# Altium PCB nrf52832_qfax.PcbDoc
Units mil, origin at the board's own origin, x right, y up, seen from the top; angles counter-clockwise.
Board outline 700 x 538.01 mil, 2 copper layers (Top Layer, Bottom Layer), stack 65.8 mil thick; 18 components, 44 nets, 86 pads, 53 vias.
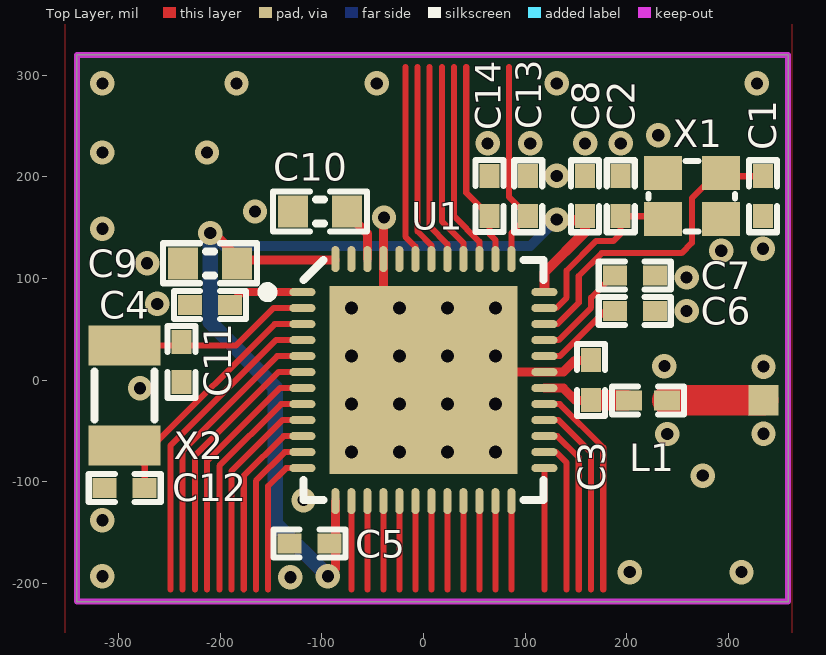
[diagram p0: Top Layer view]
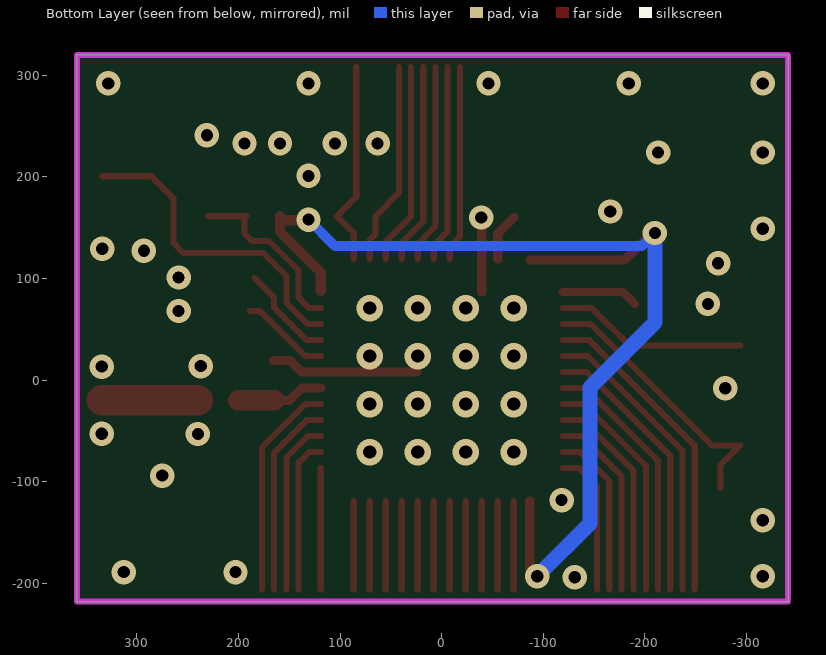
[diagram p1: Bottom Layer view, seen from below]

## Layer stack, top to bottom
Top Solder: solder mask 0.4, Solder Resist, Dk 3.5
Top Layer: signal copper 1.4
Dielectric1: core 63, FR-4, Dk 4.8
Bottom Layer: signal copper 1.4
Bottom Solder: solder mask 0.4, Solder Resist, Dk 3.5

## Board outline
-341,-218 359,-218 359,320.01 -341,320.01

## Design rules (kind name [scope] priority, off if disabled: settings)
AssemblyTestPointUsage [All] p0: scope1count=1 scope1_0_kind=Board scope1_0_value=Board scope2count=1 scope2_0_kind=Board scope2_0_value=Board commentlength=0
AssemblyTestpoint [All] p0: scope1count=1 scope1_0_kind=Board scope1_0_value=Board scope2count=1 scope2_0_kind=Board scope2_0_value=Board commentlength=0
Clearance Polygon [All] p0 off: scope1count=1 scope1_0_kind=Board scope1_0_value=Board scope2count=1 scope2_0_kind=Board scope2_0_value=Board commentlength=112 gap=10 // Protel DXP Scope 1 Expression Was: (InNamedPolygon('Top_Layer-GND')) or (InNamedPolygon('Bottom_Layer-GND'))
Clearance Polygon_ANT [All] p0 off: scope1count=1 scope1_0_kind=Board scope1_0_value=Board scope2count=1 scope2_0_kind=Net scope2_0_value=RF commentlength=112 gap=5 // Protel DXP Scope 1 Expression Was: (InNamedPolygon('Top_Layer-GND')) or (InNamedPolygon('Bottom_Layer-GND'))
Clearance [All] p0: scope1count=1 scope1_0_kind=Board scope1_0_value=Board scope2count=1 scope2_0_kind=Board scope2_0_value=Board commentlength=0 gap=6
Clearance Polygon_ANT [(InNamedPolygon('Top_Layer-GND')) or (InNamedPolygon('Bottom_Layer-GND')) vs InNet('RF')] p1: gap=5 ignorepadtopadclearanceinfootprint=FALSE except(0: Arc-Hole Track-Hole SMDPad-Hole THPad-Hole Via-Hole Fill-Hole Poly-Hole Region-Hole Text-Hole)
Clearance Polygon [(InNamedPolygon('Top_Layer-GND')) or (InNamedPolygon('Bottom_Layer-GND'))] p2: gap=10 ignorepadtopadclearanceinfootprint=FALSE except(0: Arc-Hole Track-Hole SMDPad-Hole THPad-Hole Via-Hole Fill-Hole Poly-Hole Region-Hole Text-Hole)
Clearance [All] p3: gap=6 ignorepadtopadclearanceinfootprint=FALSE except(0: Arc-Hole Track-Hole SMDPad-Hole THPad-Hole Via-Hole Fill-Hole Poly-Hole Region-Hole Text-Hole)
ComponentClearance [All] p0 off: scope1count=1 scope1_0_kind=Board scope1_0_value=Board scope2count=1 scope2_0_kind=Board scope2_0_value=Board commentlength=0 gap=10 collisioncheckmode=3
ComponentClearance [All] p1 off: gap=10 collisioncheckmode=3 verticalgap=10 showdistances=FALSE
DiffPairsRouting [All] p0: scope1count=1 scope1_0_kind=Board scope1_0_value=Board scope2count=1 scope2_0_kind=Board scope2_0_value=Board commentlength=0
FabricationTestPointUsage TestPointUsage [All] p0: scope1count=1 scope1_0_kind=Board scope1_0_value=Board scope2count=1 scope2_0_kind=Board scope2_0_value=Board commentlength=0 valid=0 allowmultiple=FALSE
FabricationTestPointUsage TestPointUsage [All] p1: valid=0 allowmultiple=FALSE
FabricationTestpoint Testpoint [All] p0: scope1count=1 scope1_0_kind=Board scope1_0_value=Board scope2count=1 scope2_0_kind=Board scope2_0_value=Board commentlength=0 side=3 testpointundercomponent=TRUE minsize=40 maxsize=100 preferedsize=60 minholesize=0 maxholesize=40 preferedholesize=32 testpointgrid=1
FabricationTestpoint Testpoint [All] p1: side=3 testpointundercomponent=TRUE minsize=40 maxsize=100 preferedsize=60 minholesize=0 maxholesize=40 preferedholesize=32 testpointgrid=1 allowsidetop=TRUE allowsidebottom=TRUE usegrid=TRUE gridtolerance=0.01
FanoutControl Fanout_Default [All] p0: scope1count=1 scope1_0_kind=Board scope1_0_value=Board scope2count=1 scope2_0_kind=Board scope2_0_value=Board commentlength=30 // Fanout_Default (Default Rule)
FanoutControl Fanout_Small [All] p0 off: scope1count=1 scope1_0_kind=Board scope1_0_value=Board scope2count=1 scope2_0_kind=Board scope2_0_value=Board commentlength=84 // Protel DXP Scope 1 Expression Was: (CompPinCount < 5)   Fanout_Small (Default Rule)
FanoutControl Fanout_SOIC [All] p0 off: scope1count=1 scope1_0_kind=Board scope1_0_value=Board scope2count=1 scope2_0_kind=Board scope2_0_value=Board commentlength=71 // Protel DXP Scope 1 Expression Was: IsSOIC   Fanout_SOIC (Default Rule)
FanoutControl Fanout_LCC [All] p0 off: scope1count=1 scope1_0_kind=Board scope1_0_value=Board scope2count=1 scope2_0_kind=Board scope2_0_value=Board commentlength=69 // Protel DXP Scope 1 Expression Was: IsLCC   Fanout_LCC (Default Rule)
FanoutControl Fanout_BGA [All] p0 off: scope1count=1 scope1_0_kind=Board scope1_0_value=Board scope2count=1 scope2_0_kind=Board scope2_0_value=Board commentlength=69 // Protel DXP Scope 1 Expression Was: IsBGA   Fanout_BGA (Default Rule)
Height [All] p0 off: scope1count=1 scope1_0_kind=Board scope1_0_value=Board scope2count=1 scope2_0_kind=Board scope2_0_value=Board commentlength=0
Height [All] p1 off: minheight=0 maxheight=1000 prefheight=500
HoleSize [All] p0: scope1count=1 scope1_0_kind=Board scope1_0_value=Board scope2count=1 scope2_0_kind=Board scope2_0_value=Board commentlength=0 absolutevalues=TRUE maxlimit=160 minlimit=12 maxpercent=80.000 minpercent=20.000
HoleSize [All] p1: absolutevalues=TRUE maxlimit=160 minlimit=12 maxpercent=80.000 minpercent=20.000
HoleToHoleClearance [All] p0: scope1count=1 scope1_0_kind=Board scope1_0_value=Board scope2count=1 scope2_0_kind=Board scope2_0_value=Board commentlength=0
LayerPairs [All] p0: scope1count=1 scope1_0_kind=Board scope1_0_value=Board scope2count=1 scope2_0_kind=Board scope2_0_value=Board commentlength=0 enforce=TRUE
MinimumAnnularRing [All] p0 off: scope1count=1 scope1_0_kind=Board scope1_0_value=Board scope2count=1 scope2_0_kind=Board scope2_0_value=Board commentlength=0 minimumring=6
MinimumAnnularRing [All] p1 off: minimumring=6
MinimumSolderMaskSliver [All] p0: scope1count=1 scope1_0_kind=Board scope1_0_value=Board scope2count=1 scope2_0_kind=Board scope2_0_value=Board commentlength=0
NetAntennae [All] p0: scope1count=1 scope1_0_kind=Board scope1_0_value=Board scope2count=1 scope2_0_kind=Board scope2_0_value=Board commentlength=0
PasteMaskExpansion [All] p0: scope1count=1 scope1_0_kind=Board scope1_0_value=Board scope2count=1 scope2_0_kind=Board scope2_0_value=Board commentlength=0 expansion=0
PlaneClearance [All] p0: scope1count=1 scope1_0_kind=Board scope1_0_value=Board scope2count=1 scope2_0_kind=Board scope2_0_value=Board commentlength=0 clearance=20
PlaneConnect [All] p0: scope1count=1 scope1_0_kind=Board scope1_0_value=Board scope2count=1 scope2_0_kind=Board scope2_0_value=Board commentlength=0 planeconnectstyle=Relief reliefexpansion=20 reliefentries=4 reliefconductorwidth=10 reliefairgap=10
PolygonConnect [All] p0: scope1count=1 scope1_0_kind=Board scope1_0_value=Board scope2count=1 scope2_0_kind=Board scope2_0_value=Board commentlength=0 connectstyle=Relief reliefconductorwidth=10 reliefentries=4 polygonreliefangle="90 Angle"
PolygonConnect PolygonConnect_1 [All] p0 off: scope1count=1 scope1_0_kind=Board scope1_0_value=Board scope2count=1 scope2_0_kind=Board scope2_0_value=Board commentlength=59 connectstyle=Direct reliefconductorwidth=10 reliefentries=4 polygonreliefangle="90 Angle" // Protel DXP Scope 1 Expression Was: isVia and innet(gnd)
PolygonConnect PolygonConnect_1 [isVia and innet(gnd)] p1: connectstyle=Direct reliefconductorwidth=10 reliefentries=4 polygonreliefangle="90 Angle" airgapwidth=10
PolygonConnect [All] p2: connectstyle=Relief reliefconductorwidth=10 reliefentries=4 polygonreliefangle="90 Angle" airgapwidth=10
RoutingCorners [All] p0: scope1count=1 scope1_0_kind=Board scope1_0_value=Board scope2count=1 scope2_0_kind=Board scope2_0_value=Board commentlength=0 cornerstyle=45-Degree minsetback=100 maxsetback=100
RoutingLayers [All] p0: scope1count=1 scope1_0_kind=Board scope1_0_value=Board scope2count=1 scope2_0_kind=Board scope2_0_value=Board commentlength=0 top layer=Automatic bottom layer=Automatic
RoutingPriority [All] p0: scope1count=1 scope1_0_kind=Board scope1_0_value=Board scope2count=1 scope2_0_kind=Board scope2_0_value=Board commentlength=0
RoutingTopology [All] p0: scope1count=1 scope1_0_kind=Board scope1_0_value=Board scope2count=1 scope2_0_kind=Board scope2_0_value=Board commentlength=0 topology=Shortest
RoutingVias [All] p0: scope1count=1 scope1_0_kind=Board scope1_0_value=Board scope2count=1 scope2_0_kind=Board scope2_0_value=Board commentlength=0 holewidth=16 width=32 viastyle="Through Hole" minholewidth=10 minwidth=10 maxholewidth=28 maxwidth=50
RoutingVias [All] p1: holewidth=16 width=32 viastyle="Through Hole" minholewidth=10 minwidth=10 maxholewidth=28 maxwidth=50
ShortCircuit [All] p0: scope1count=1 scope1_0_kind=Board scope1_0_value=Board scope2count=1 scope2_0_kind=Board scope2_0_value=Board commentlength=0 allowed=FALSE
SilkToBoardRegionClearance [All] p0: scope1count=1 scope1_0_kind=Board scope1_0_value=Board scope2count=1 scope2_0_kind=Board scope2_0_value=Board commentlength=0
SilkToSilkClearance [All] p0: scope1count=1 scope1_0_kind=Board scope1_0_value=Board scope2count=1 scope2_0_kind=Board scope2_0_value=Board commentlength=0
SilkToSolderMaskClearance SilkscreenOverComponentPads [All] p0 off: scope1count=1 scope1_0_kind=Board scope1_0_value=Board scope2count=1 scope2_0_kind=Board scope2_0_value=Board commentlength=44 // Protel DXP Scope 1 Expression Was: IsPad
SilkToSolderMaskClearance SilkscreenOverComponentPads [IsPad] p1: minsilkscreentomaskgap=10 clearancetoexposedcopper=TRUE
SolderMaskExpansion [All] p0: scope1count=1 scope1_0_kind=Board scope1_0_value=Board scope2count=1 scope2_0_kind=Board scope2_0_value=Board commentlength=0 expansion=3
SolderMaskExpansion [All] p1: expansion=3
UnRoutedNet [All] p0: scope1count=1 scope1_0_kind=Board scope1_0_value=Board scope2count=1 scope2_0_kind=Board scope2_0_value=Board commentlength=0
UnpouredPolygon [All] p0: scope1count=1 scope1_0_kind=Board scope1_0_value=Board scope2count=1 scope2_0_kind=Board scope2_0_value=Board commentlength=0
Width [All] p0: scope1count=1 scope1_0_kind=Board scope1_0_value=Board scope2count=1 scope2_0_kind=Board scope2_0_value=Board commentlength=0 maxlimit=100 minlimit=6 preferedwidth=6
Width [All] p1: maxlimit=100 minlimit=6 preferedwidth=6
24 further rules are at their usual default settings.

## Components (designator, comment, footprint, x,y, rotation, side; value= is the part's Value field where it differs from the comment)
C1 "12pF" CAPC1005X04L 334.15,181.01 r270 top
C2 "12pF" CAPC1005X04L 194.15,181.01 r90 top
C3 "0.8pF" CAPC1005X04L 165,0 r270 top
C4 "100nF" CAPC1005X04L -210,74 r180 top
C5 "100nF" CAPC1005X04L -112,-161 r180 top
C6 "N.C." CAPC1005X04L 208,68 r180 top
C7 "100pF" CAPC1005X04L 208,103 r0 top
C8 "100nF" CAPC1005X04L 159.15,181.01 r90 top
C9 "4.7µF" CAPC1608X06L -210,115 r180 top
C10 "1.0µF" CAPC1608X06L -101.85,166.01 r0 top
C11 "12pF" CAPC1005X04L -238,18 r270 top
C12 "12pF" CAPC1005X04L -294,-106 r180 top
C13 "" CAPC1005X04L 103.15,181.01 r90 top
C14 "12pF" CAPC1005X04L 65.15,181.09 r90 top
L1 "3.9nH" INDC1005X04L 221,-20 r0 top
U1 "nRF52832-QFAA" QFN40P600X600X90-48N 0,0 r0 top locked
X1 "32MHz" BT-XTAL_2016 264.15,181.01 r180 top
X2 "32.768kHz" XTAL_3215 -294,-15 r270 top

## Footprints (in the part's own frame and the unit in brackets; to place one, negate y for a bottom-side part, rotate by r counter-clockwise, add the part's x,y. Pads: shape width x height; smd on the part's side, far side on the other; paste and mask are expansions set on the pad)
BT-XTAL_2016 [mm] "Crystal 2.0 x 1.6 mm"
  rect 0.95x0.85 smd: 1(-0.725,-0.575) 2(0.725,-0.575) 3(0.725,0.575) 4(-0.725,0.575)
  silkscreen extent -1.08,-0.88 1.08,0.88
CAPC1005X04L [mm] "Chip Capacitor, 2-Leads, Body 1.0x0.5mm, IPC High Density"
  rect 0.6x0.5 smd: 1(-0.5,0) 2(0.5,0)
  silkscreen extent -0.9,-0.35 0.9,0.35
CAPC1608X06L [mm] "Chip Capacitor, 2-Leads, Body 1.6x0.8mm, IPC High Density"
  rect 0.75x0.8 smd: 1(-0.675,0) 2(0.675,0)
  silkscreen extent -1.17,-0.5 1.17,0.5
INDC1005X04L [mm] "Chip Inductor, 2-Leads, Body 1.0x0.5mm, IPC High Density"
  rect 0.65x0.5 smd: 1(-0.475,0) 2(0.475,0)
  silkscreen extent -0.9,-0.35 0.9,0.35
QFN40P600X600X90-48N [mm] "QFN, 48-Leads, Body 6,0x6,0mm (max), Pitch 0,40mm, IPC Medium Density"
  oval 0.65x0.2 smd: 1(-3.025,2.2) 2(-3.025,1.8) 3(-3.025,1.4) 4(-3.025,1) 5(-3.025,0.6) 6(-3.025,0.2) 7(-3.025,-0.2) 8(-3.025,-0.6) 9(-3.025,-1) 10(-3.025,-1.4) 11(-3.025,-1.8) 12(-3.025,-2.2) 25(3.025,-2.2) 26(3.025,-1.8) 27(3.025,-1.4) 28(3.025,-1) 29(3.025,-0.6) 30(3.025,-0.2) 31(3.025,0.2) 32(3.025,0.6) 33(3.025,1) 34(3.025,1.4) 35(3.025,1.8) 36(3.025,2.2)
  oval 0.2x0.65 smd: 13(-2.2,-3.025) 14(-1.8,-3.025) 15(-1.4,-3.025) 16(-1,-3.025) 17(-0.6,-3.025) 18(-0.2,-3.025) 19(0.2,-3.025) 20(0.6,-3.025) 21(1,-3.025) 22(1.4,-3.025) 23(1.8,-3.025) 24(2.2,-3.025) 37(2.2,3.025) 38(1.8,3.025) 39(1.4,3.025) 40(1,3.025) 41(0.6,3.025) 42(0.2,3.025) 43(-0.2,3.025) 44(-0.6,3.025) 45(-1,3.025) 46(-1.4,3.025) 47(-1.8,3.025) 48(-2.2,3.025)
  rect 4.7x4.7 smd: 49(0,0)
  silkscreen extent -4.02,-3 3,3
XTAL_3215 [mm] "XTAL SMD 3.2 x 1.5 mm"
  rect 1x1.8 smd: 1(-1.25,0) 2(1.25,0)
  silkscreen extent -0.6,-0.75 0.6,0.75

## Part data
C1 C2 C11 C12 C13 C14: library part C0402-12p, "Capacitor, NP0, ±2%"
C3: library part C0402-0.8p, "Capacitor, NP0, ±5%"
C4 C5 C8: library part C0402-100n, "Capacitor, X7R, ±10%"
C6: library part C0402-N.C., "Not mounted"
C7: library part C0402-100p, "Capacitor, NP0, ±5%"
C9: library part C0603-4µ7, "Capacitor, X5R, ±10%"
C10: library part C0603-1µ0, "Capacitor, X7R, ±10%"
L1: library part L0402-3n9, "High frequency chip inductor ±5%"
U1: "Multi-protocol Bluetooth Low Energy, ANT and 2.4GHz proprietary system-on-chip"
X1: library part XTAL_SMD2016_32MHz_8pF_General, "XTAL SMD 2016, 32MHz, Cl=8pF, Total Tol: ±40ppm"
X2: library part XTAL_SMD3215_32.768kHz_9pF_General, "XTAL SMD 3215, 32.768kHz, Cl=9pF, Total Tol: ±50ppm"

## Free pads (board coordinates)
  rect 30x30 smd: 0(334.7,-19.75)

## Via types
v1: diameter 24, hole 12, Top Layer to Bottom Layer, tented both sides, 37 vias
v2: diameter 25.98, hole 12.99, Top Layer to Bottom Layer, tented both sides, 16 vias

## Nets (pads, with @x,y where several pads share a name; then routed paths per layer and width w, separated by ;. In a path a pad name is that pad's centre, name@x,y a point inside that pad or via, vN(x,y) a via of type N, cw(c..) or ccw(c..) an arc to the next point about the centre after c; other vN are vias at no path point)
DEC1: C4.1 U1.1 | length 76
  Top Layer w8: C4.1@-190.16,74.76 -178.31,86.61 U1.1
DEC2: C6.2 U1.32 | length 88.3
  Top Layer w6: U1.32 134.3,23.62 178.67,68 C6.2@189,68
DEC3: C7.1 U1.33 | length 96
  Top Layer w6: U1.33 133.07,39.37 165,71.3 165,81.19 C7.1@184.06,100.25
DEC4: C10.2 U1.46 | length 47.8
  Top Layer w9: C10.2@-71.26,160.19 -55.12,144.05 U1.46
GND: C1.2 C2.2 C3.1 C4.2 C5.2 C6.1 C7.2 C8.2 C9.2 C10.1 C11.2 C12.2 C13.2 C14.2 U1.31 U1.45 U1.49 X1.2 X1.4 | length 219.1
  Top Layer w9: U1.49@-39.37,86.61 U1.45 v1@-39.37,160.01 ; U1.49@24.31,8 137.77,8 149.06,19.3 C3.1@165.31,19.3
  other v1: -131,-194 -316,-193 203,-189 313,-189 -316,-138 -118,-118.11 275,-94 240,-53 334.7,-52.75 -279,-8 334.7,13.25 237.16,13.76 259,68 -262,75 259,101 -272,115 293.15,127.32 334.15,129.32 -316,149 -38.85,160.01 -165.85,166.01 131.15,201.01 -316,224 -213,224 63.15,233.01 105.15,233.01 159.15,233.01 194.15,233.01 231.15,241.01 -316,292 -184,292 -46,292 131.15,292.01 328.16,292
  other v2: -70.87,-70.87 -23.62,-70.87 23.62,-70.87 70.87,-70.87 -70.87,-23.62 -23.62,-23.62 23.62,-23.62 70.87,-23.62 -70.87,23.62 -23.62,23.62 23.62,23.62 70.87,23.62 -70.87,70.87 -23.62,70.87 23.62,70.87 70.87,70.87
NetC3_2: C3.2 L1.1 U1.30 | length 86.6
  Top Layer w9: U1.30 137.79,-7.87 149.99,-20.07 C3.2@165.32,-20.07
  Top Layer w20: C3.2@165,-19.87 L1.1@200.31,-19.87
P0.00/XL1: C11.1 U1.2 X2.1 | length 190.1
  Top Layer w6: X2.1 -184.36,34.21 -147.71,70.87 U1.2
P0.01/XL2: C12.1 U1.3 X2.2 | length 274.3
  Top Layer w6: C12.1 -274.32,-83.9 X2.2 -265.82,-64.21 -146.49,55.12 U1.3
P0.02/AIN0: U1.4 | length 314.3
  Top Layer w6: -249,-205.81 -249,-64.39 -145.24,39.37 U1.4
P0.03/AIN1: U1.5 | length 292.8
  Top Layer w6: -236.98,-205.81 -236.98,-69.37 -143.98,23.62 U1.5
P0.04/AIN2: U1.6 | length 271.4
  Top Layer w6: -224.96,-205.81 -224.96,-74.35 -142.73,7.87 U1.6
P0.05/AIN3: U1.7 | length 249.8
  Top Layer w6: -212.85,-205.81 -212.85,-79.37 -141.36,-7.87 U1.7
P0.06: U1.8 | length 228.4
  Top Layer w6: -200.85,-205.81 -200.85,-84.34 -140.14,-23.62 U1.8
P0.07: U1.9 | length 206.9
  Top Layer w6: -188.85,-205.81 -188.85,-89.31 -138.92,-39.37 U1.9
P0.08: U1.10 | length 185.5
  Top Layer w6: -176.85,-205.81 -176.85,-94.28 -137.7,-55.12 U1.10
P0.09: U1.11 | length 164.1
  Top Layer w6: -164.85,-205.81 -164.85,-99.25 -136.47,-70.87 U1.11
P0.10: U1.12 | length 142.6
  Top Layer w6: -152.85,-205.81 -152.85,-104.22 -135.25,-86.61 U1.12
P0.11: U1.14 | length 86.9
  Top Layer w6: -70.87,-206 U1.14
P0.12: U1.15 | length 86.9
  Top Layer w6: -55.12,-206 U1.15
P0.13: U1.16 | length 86.9
  Top Layer w6: -39.37,-206 U1.16
P0.14: U1.17 | length 86.9
  Top Layer w6: -23.62,-206 U1.17
P0.15: U1.18 | length 86.9
  Top Layer w6: -7.87,-206 U1.18
P0.16: U1.19 | length 86.9
  Top Layer w6: 7.87,-206 U1.19
P0.17: U1.20 | length 86.9
  Top Layer w6: 23.62,-206 U1.20
P0.18: U1.21 | length 86.9
  Top Layer w6: 39.37,-206 U1.21
P0.19: U1.22 | length 86.9
  Top Layer w6: 55.12,-206 U1.22
P0.20: U1.23 | length 86.9
  Top Layer w6: 70.87,-206 U1.23
P0.21: U1.24 | length 86.9
  Top Layer w6: 86.61,-206 U1.24
P0.22: U1.27 | length 172.4
  Top Layer w6: U1.27 131.85,-55.12 152.89,-76.16 152.89,-206
P0.23: U1.28 | length 193.8
  Top Layer w6: U1.28 133.07,-39.37 165,-71.3 165,-206
P0.24: U1.29 | length 215.3
  Top Layer w6: U1.29 134.3,-23.62 177,-66.33 177,-206
P0.25: C13.1 U1.37 | length 203.6
  Top Layer w6: 84.15,308.01 84.15,180.32 C13.1 86.61,144.78 U1.37
P0.26: C14.1 U1.38 | length 201.9
  Top Layer w6: 42.15,308.01 42.15,184.41 C14.1@64.15,162.41 ; C14.1@64.15,161.32 C14.1@64.15,162.41 ; U1.38 70.87,138.02 65.15,143.73 C14.1 C14.1@64.15,162.41
P0.27: U1.39 | length 199.3
  Top Layer w6: 30.15,308.01 30.15,161.32 55.12,136.35 U1.39
P0.28/AIN4: U1.40 | length 197.7
  Top Layer w6: 18.15,308.01 18.15,156.29 39.37,135.07 U1.40
P0.29/AIN5: U1.41 | length 196.1
  Top Layer w6: 6.15,308.01 6.15,151.32 23.62,133.85 U1.41
P0.30/AIN6: U1.42 | length 194.6
  Top Layer w6: -5.85,308.01 -5.85,146.32 7.87,132.6 U1.42
P0.31/AIN7: U1.43 | length 193
  Top Layer w6: -17.85,308.01 -17.85,141.32 -7.87,131.35 U1.43
RF: L1.2 pad.0 | length 94.7
  Top Layer w30: L1.2@240.02,-19.75 pad.0
SWDCLK: U1.25 | length 119.4
  Top Layer w6: 119.09,-206 U1.25
SWDIO: U1.26 | length 150.8
  Top Layer w6: U1.26 130.5,-70.87 140.89,-81.26 140.89,-206
VDD_NRF: C5.1 C8.1 C9.1 U1.13 U1.36 U1.48 | length 1075.8
  Top Layer w9: v1(-209.84,144.76) -206.58,144.76 -179.92,118.11 U1.48@-87,118.11 ; v1(-94,-193) -86.61,-185.61 U1.13
  Top Layer w10: U1.36@119.09,88.01 119.09,105.95 159.15,146 C8.1 159.15,157.32 131.84,157.32 v1(131.15,158.01)
  Bottom Layer w10: v1(-209.84,144.76) -197.08,132 105.14,132 v1(131.15,158.01)
  Bottom Layer w15: v1(-209.84,144.76) -209.84,56.66 -145.95,-7.24 -145.95,-141.05 v1(-94,-193)
XC1: C1.1 U1.34 X1.1 | length 316.5
  Top Layer w6: U1.34 131.85,55.12 152.89,76.16 152.89,102.47 175.42,125.01 254.15,125.01 264.15,135.01 264.15,179.01 285.84,200.69 C1.1
XC2: C2.1 U1.35 X1.3 | length 175.6
  Top Layer w6: U1.35 130.5,70.87 140.89,81.26 140.89,107.9 169.99,137.01 187.16,137.01 194.14,144 C2.1@194.14,161.01 ; C2.1@192.15,161.32 X1.3@229.81,161.32
pads on no net: U1.44 U1.47

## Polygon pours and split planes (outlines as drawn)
GND on Top Layer "Top_Layer-GND" (solid, remove dead copper, pour order 1000): -353,410 -353,-266.19 363,-266.19 363,410 -353,410
GND on Bottom Layer "Bottom_Layer-GND" (solid, remove dead copper, pour order 1001): -373,400 -373,-266.19 394,-266.19 394,400 -373,400

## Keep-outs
Keep-Out Layer:
  the board outline again, w6

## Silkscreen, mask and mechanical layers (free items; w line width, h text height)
Mechanical 1:
  the board outline again, w6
